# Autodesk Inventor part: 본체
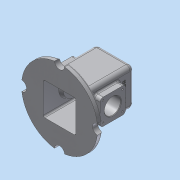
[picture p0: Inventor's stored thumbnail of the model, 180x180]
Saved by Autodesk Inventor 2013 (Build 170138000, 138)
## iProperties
Created: 2018-07
Part Number: 본체
Material: 알루미늄 6061
Document SubType Name: Modeling
Designer: Administrator
Density: 2.71 g/cm^3
Mass: 912.692 g
Surface Area: 1017.53 cm^2
Volume: 336.787 cm^3
Author: Administrator
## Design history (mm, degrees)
sketch "스케치1"
  geometry: L1 (37, -37)-(-37, -37); L2 (-37, -37)-(-37, 37); L3 (-37, 37)-(37, 37); L4 (37, 37)-(37, -37); L5 (37, -37)-(-37, 37); L6 (-37, -37)-(37, 37); 1 further point
  constraints: 12 end point, 2 midpoint, 2 parallel, 1 horizontal, 1 perpendicular
  dimensions: "d0" = 74 distance of L1.start L1.end; "d2" = 74 distance of L1.end L2.end
extrude "돌출1" new body sketch "스케치1" distance "d3" = 110; taper "d4" = 0 deg
fillet "모깎기1" dims "d5" = 8
fillet "모깎기2" dims "d6" = 8
feature "쉘1" dims "d7" = 5
node "작업 평면1"
sketch "스케치3"
  geometry: C1 r 17.5 at (0, 0); 1 further point
  constraints: 1 centre point, 1 coincident
  dimensions: "d9" = 35 diameter of C1
extrude "돌출2" join sketch "스케치3" stored distance "d11" = 110; taper "d12" = 0 deg
node "작업 평면2"
sketch "스케치4"
  geometry: L1 (-20, 20)-(20, 20); L2 (20, 20)-(20, -20); L3 (20, -20)-(-20, -20); L4 (-20, -20)-(-20, 20); L5 (-20, 20)-(20, -20); L6 (20, 20)-(-20, -20); C1 r 17.5 at (0, 0) reference; 1 further point
  constraints: 12 end point, 2 midpoint, 2 parallel, 1 horizontal, 1 perpendicular
  dimensions: "d14" = 40 distance of L2.end L3.end; "d15" = 40 distance of L1.end L2.end
extrude "돌출3" join sketch "스케치4" stored distance "d16" = 110; taper "d17" = 0 deg
fillet "모깎기3" dims "d18" = 3
fillet "모깎기4" dims "d19" = 3
hole "구멍1" diameter "d22" = 21; stored, may be unused: countersink angle "d26" = 90 deg, drill point angle "d28" = 118 deg; dims "d20" = 10, "d21" = 10, "d23" = 6, "d24" = 28, "d25" = 4, "d27" = 8
node "작업 평면3"
sketch "스케치5"
  geometry: L1 (-80, 25)-(-30, 25); L2 (-30, 25)-(-30, -25); L3 (-30, -25)-(-80, -25); L4 (-80, -25)-(-80, 25); L5 (-80, 25)-(-30, -25); L6 (-30, 25)-(-80, -25); L7 (0, 29)-(0, -29) reference; 3 further points
  constraints: 12 end point, 4 midpoint, 2 parallel, 1 horizontal, 1 horizontal alignment, 1 perpendicular
  dimensions: "d31" = 50 distance of L1.start L1.end; "d33" = 50 distance of L1.end L2.end; "d34" = 55 distance of point (0, 0) point (-55, 0)
extrude "돌출4" join sketch "스케치5" stored distance "d35" = 110; taper "d36" = 0 deg
sketch "스케치6"
  geometry: L1 (58, 0)-(0, 0) reference; C1 r 25 at (29, 55); 2 further points
  constraints: 1 centre point, 1 midpoint, 1 vertical alignment
  dimensions: "d37" = 50 diameter of C1; "d38" = 55 distance of point (29, 0) C1.centre
extrude "돌출5" join sketch "스케치6" distance "d39" = 7; taper "d40" = -20 deg
hole "구멍2" diameter "d43" = 32; stored, may be unused: countersink angle "d47" = 90 deg, drill point angle "d49" = 118 deg; dims "d41" = 10, "d42" = 10, "d44" = 6, "d45" = 28, "d46" = 4, "d48" = 8
fillet "모깎기5" dims "d50" = 6
fillet "모깎기6" dims "d51" = 3
sketch "스케치7"
  geometry: A1 r 6 centre (44, 38) between (50, 38) and (44, 44) reference; A2 r 6 centre (6, 38) between (6, 44) and (0, 38) reference; A3 r 6 centre (6, 0) between (0, 0) and (6, -6) reference; A4 r 6 centre (44, 0) between (44, -6) and (50, 0) reference; 5 further points
  constraints: 4 coincident
hole "구멍3" sketch "스케치7" at (6, 38), (44, 38), (6, 0), (44, 0) diameter "d52" = 3.242; stored, may be unused: countersink angle "d56" = 90 deg, drill point angle "d58" = 118 deg; dims "d53" = 8, "d54" = 28, "d55" = 4, "d57" = 10
chamfer "모따기1" distance "d59" = 1; stored, may be unused: second distance "d60" = 2, angle "d61" = 45 deg
sketch "스케치8"
  geometry: L1 (-32, -29)-(-32, 29) reference; L2 (-29, 32)-(29, 32) reference; L3 (32, 29)-(32, -29) reference; L4 (29, -32)-(-29, -32) reference; C1 r 75 at (0, 0); A1 r 3 centre (-29, -29) between (-32, -29) and (-29, -32) reference; A2 r 3 centre (-29, 29) between (-29, 32) and (-32, 29) reference; A3 r 3 centre (29, 29) between (32, 29) and (29, 32) reference; A4 r 3 centre (29, -29) between (29, -32) and (32, -29) reference; 1 further point
  constraints: 1 centre point, 1 coincident
  dimensions: "d62" = 150 diameter of C1
extrude "돌출6" join sketch "스케치8" distance "d63" = 10; taper "d64" = 0 deg
sketch "스케치9"
  geometry: C1 r 10 at (0, 75); C2 r 10 at (-75, 0); C3 r 10 at (0, -75); C4 r 10 at (75, 0); 1 further point
  constraints: 4 centre point, 2 vertical alignment, 10 other
  dimensions: "d65" = 20 diameter of C1; "d68" = 360 deg dimension on point (0, 0) C1.centre (derived)
extrude "돌출7" cut sketch "스케치9" stored distance "d70" = 0; taper "d71" = 0 deg
fillet "모깎기7" dims "d73" = 3
sketch "스케치10"
  geometry: L1 (66, -89)-(66, 0) reference; L2 (46.5, 18)-(11.5, 18) reference; 2 further points
  constraints: 1 other
  dimensions: "d74" = 37 distance from line of L1 point (29, -12); "d75" = 30 distance from line of L2 point (29, -12)
feature "엠보싱1" sketch "스케치10" dims "d0" = 74, "d2" = 74, "d76" = 0.5, "d77" = 0
node "솔리드1"
mirror "대칭1"
mirror "대칭2"
other parameters: "d13" = -3
